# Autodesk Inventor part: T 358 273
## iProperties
Created: 2005-10
Part Number: T 358 273
Material: 1.0718
Document SubType Name: Modeling
Designer: I.Baliuc
Manufacturer: Standard
Standards Organization: Custom
Description: Scheibe
Density: 7.84 g/cm^3
Title: Scheibe
Company: Mayer & Müller AG Schaltgeräte
Author: T.Messerschmitt
Comments: Schaltwelle Trenner
Revision Number: 358273
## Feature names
1. Extrusion2
